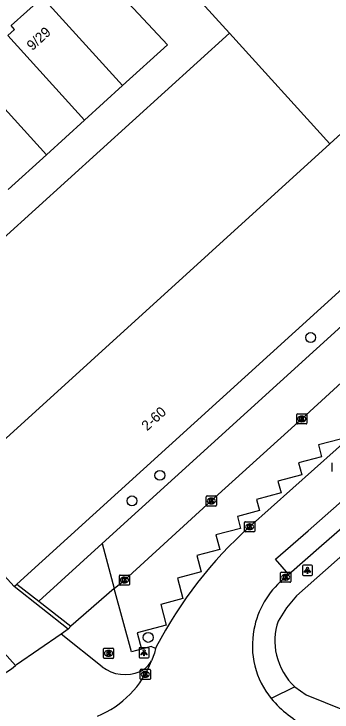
# Model space of a CAD drawing. Extents: x 161354 to 161876, y 382161 to 382804.
# Drawn here: x 161643.4 to 161674.9, y 382511.3 to 382580.4 of the extents above; entities that cross this region are included whole.
import ezdxf

# ---------------------------------------------------------------- set-up
doc = ezdxf.new("R2010")
doc.units = 0
for name, color, linetype in [('IMGEO_Boom', 7, 'Continuous'), ('IMGEO_Kolk', 7, 'Continuous'), ('IMGEO_Lichtpunt', 7, 'Continuous'), ('IMGEO_Muur', 7, 'Continuous'), ('IMGEO_Pand', 7, 'Continuous'), ('IMGEO_Pand_nummerreeks', 7, 'Continuous'), ('IMGEO_Parkeervlak_gesloten', 7, 'Continuous'), ('IMGEO_Parkeervlak_open', 7, 'Continuous'), ('IMGEO_Rijbaan_lokaal_gesloten', 7, 'Continuous'), ('IMGEO_Rijbaan_lokaal_open', 7, 'Continuous'), ('IMGEO_Rioolput', 7, 'Continuous'), ('IMGEO_Voetpad_open', 7, 'Continuous')]:
    doc.layers.add(name, color=color, linetype=linetype)

msp = doc.modelspace()

# ---------------------------------------------------------------- linework, layer by layer
at = {"layer": 'IMGEO_Boom'}
for centre in [(161672.751, 382548.367), (161657.819, 382534.735), (161655.061, 382532.208), (161656.668, 382518.703)]:
    msp.add_circle(centre, 0.489, dxfattribs=at)
at = {"layer": 'IMGEO_Kolk'}
for p, q in [((161671.374, 382539.891), (161671.374, 382540.743)), ((161671.449, 382540.817), (161672.301, 382540.817)), ((161671.862, 382540.597), (161671.887, 382540.597)), ((161672.375, 382540.743), (161672.375, 382539.891)), ((161672.301, 382539.817), (161671.449, 382539.817)), ((161671.885, 382540.037), (161671.86, 382540.037)), ((161662.415, 382531.773), (161662.415, 382532.625)), ((161662.49, 382532.699), (161663.342, 382532.699)), ((161662.903, 382532.479), (161662.928, 382532.479)), ((161663.416, 382532.625), (161663.416, 382531.773)), ((161663.342, 382531.699), (161662.49, 382531.699)), ((161662.926, 382531.919), (161662.901, 382531.919)), ((161666.211, 382529.218), (161666.211, 382530.07)), ((161666.286, 382530.144), (161667.138, 382530.144)), ((161667.212, 382530.07), (161667.212, 382529.218)), ((161666.722, 382529.364), (161666.697, 382529.364)), ((161666.699, 382529.924), (161666.724, 382529.924)), ((161667.138, 382529.144), (161666.286, 382529.144)), ((161653.814, 382523.95), (161653.814, 382524.802)), ((161653.889, 382524.876), (161654.741, 382524.876)), ((161654.302, 382524.656), (161654.327, 382524.656)), ((161654.815, 382524.802), (161654.815, 382523.95)), ((161669.778, 382524.229), (161669.778, 382525.081)), ((161669.853, 382525.155), (161670.705, 382525.155)), ((161670.266, 382524.935), (161670.291, 382524.935)), ((161670.779, 382525.081), (161670.779, 382524.229)), ((161654.741, 382523.876), (161653.889, 382523.876)), ((161654.325, 382524.096), (161654.3, 382524.096)), ((161670.705, 382524.155), (161669.853, 382524.155)), ((161670.289, 382524.375), (161670.264, 382524.375)), ((161655.96, 382515.548), (161656.812, 382515.548)), ((161655.885, 382514.622), (161655.885, 382515.474)), ((161656.373, 382515.328), (161656.398, 382515.328)), ((161656.886, 382515.474), (161656.886, 382514.622)), ((161656.812, 382514.548), (161655.96, 382514.548)), ((161656.396, 382514.768), (161656.371, 382514.768))]:
    msp.add_line(p, q, dxfattribs=at)
for points in [[(161671.374, 382539.891), (161671.374, 382540.743)], [(161671.449, 382540.817), (161672.301, 382540.817)], [(161671.695, 382540.517), (161671.818, 382540.517), (161671.818, 382540.366), (161671.948, 382540.517), (161672.112, 382540.517), (161671.966, 382540.366), (161672.119, 382540.117), (161671.967, 382540.117), (161671.882, 382540.281), (161671.818, 382540.214), (161671.818, 382540.117), (161671.695, 382540.117), (161671.695, 382540.517)], [(161672.375, 382540.743), (161672.375, 382539.891)], [(161672.301, 382539.817), (161671.449, 382539.817)], [(161662.415, 382531.773), (161662.415, 382532.625)], [(161662.49, 382532.699), (161663.342, 382532.699)], [(161662.736, 382532.399), (161662.859, 382532.399), (161662.859, 382532.248), (161662.989, 382532.399), (161663.153, 382532.399), (161663.007, 382532.248), (161663.16, 382531.999), (161663.008, 382531.999), (161662.923, 382532.163), (161662.859, 382532.096), (161662.859, 382531.999), (161662.736, 382531.999), (161662.736, 382532.399)], [(161663.416, 382532.625), (161663.416, 382531.773)], [(161663.342, 382531.699), (161662.49, 382531.699)], [(161666.211, 382529.218), (161666.211, 382530.07)], [(161666.286, 382530.144), (161667.138, 382530.144)], [(161667.212, 382530.07), (161667.212, 382529.218)], [(161666.532, 382529.844), (161666.655, 382529.844), (161666.655, 382529.693), (161666.785, 382529.844), (161666.949, 382529.844), (161666.803, 382529.693), (161666.956, 382529.444), (161666.804, 382529.444), (161666.719, 382529.608), (161666.655, 382529.541), (161666.655, 382529.444), (161666.532, 382529.444), (161666.532, 382529.844)], [(161667.138, 382529.144), (161666.286, 382529.144)], [(161653.814, 382523.95), (161653.814, 382524.802)], [(161653.889, 382524.876), (161654.741, 382524.876)], [(161654.135, 382524.576), (161654.258, 382524.576), (161654.258, 382524.425), (161654.388, 382524.576), (161654.552, 382524.576), (161654.406, 382524.425), (161654.559, 382524.176), (161654.407, 382524.176), (161654.322, 382524.34), (161654.258, 382524.273), (161654.258, 382524.176), (161654.135, 382524.176), (161654.135, 382524.576)], [(161654.815, 382524.802), (161654.815, 382523.95)], [(161669.778, 382524.229), (161669.778, 382525.081)], [(161669.853, 382525.155), (161670.705, 382525.155)], [(161670.099, 382524.855), (161670.222, 382524.855), (161670.222, 382524.704), (161670.352, 382524.855), (161670.516, 382524.855), (161670.37, 382524.704), (161670.523, 382524.455), (161670.371, 382524.455), (161670.286, 382524.619), (161670.222, 382524.552), (161670.222, 382524.455), (161670.099, 382524.455), (161670.099, 382524.855)], [(161670.779, 382525.081), (161670.779, 382524.229)], [(161654.741, 382523.876), (161653.889, 382523.876)], [(161670.705, 382524.155), (161669.853, 382524.155)], [(161655.96, 382515.548), (161656.812, 382515.548)], [(161655.885, 382514.622), (161655.885, 382515.474)], [(161656.206, 382515.248), (161656.329, 382515.248), (161656.329, 382515.097), (161656.459, 382515.248), (161656.623, 382515.248), (161656.477, 382515.097), (161656.63, 382514.848), (161656.478, 382514.848), (161656.393, 382515.012), (161656.329, 382514.945), (161656.329, 382514.848), (161656.206, 382514.848), (161656.206, 382515.248)], [(161656.886, 382515.474), (161656.886, 382514.622)], [(161656.812, 382514.548), (161655.96, 382514.548)]]:
    msp.add_lwpolyline(points, dxfattribs=at)
for centre, start, end in [((161671.451, 382540.741), 91.55205, 178.44795), ((161671.451, 382540.741), 91.55205, 178.44795), ((161672.299, 382540.741), 1.55205, 88.44795), ((161672.299, 382540.741), 1.55205, 88.44795), ((161671.451, 382539.893), 181.55205, 268.44795), ((161671.451, 382539.893), 181.55205, 268.44795), ((161672.299, 382539.893), 271.55205, 358.44795), ((161672.299, 382539.893), 271.55205, 358.44795), ((161662.492, 382532.623), 91.55205, 178.44795), ((161662.492, 382532.623), 91.55205, 178.44795), ((161663.34, 382532.623), 1.55205, 88.44795), ((161663.34, 382532.623), 1.55205, 88.44795), ((161662.492, 382531.775), 181.55205, 268.44795), ((161662.492, 382531.775), 181.55205, 268.44795), ((161663.34, 382531.775), 271.55205, 358.44795), ((161663.34, 382531.775), 271.55205, 358.44795), ((161666.288, 382530.068), 91.55205, 178.44795), ((161666.288, 382530.068), 91.55205, 178.44795), ((161667.136, 382530.068), 1.55205, 88.44795), ((161667.136, 382530.068), 1.55205, 88.44795), ((161666.288, 382529.22), 181.55205, 268.44795), ((161666.288, 382529.22), 181.55205, 268.44795), ((161667.136, 382529.22), 271.55205, 358.44795), ((161667.136, 382529.22), 271.55205, 358.44795), ((161653.891, 382524.8), 91.55205, 178.44795), ((161653.891, 382524.8), 91.55205, 178.44795), ((161654.739, 382524.8), 1.55205, 88.44795), ((161654.739, 382524.8), 1.55205, 88.44795), ((161669.855, 382525.079), 91.55205, 178.44795), ((161669.855, 382525.079), 91.55205, 178.44795), ((161670.703, 382525.079), 1.55205, 88.44795), ((161670.703, 382525.079), 1.55205, 88.44795), ((161653.891, 382523.952), 181.55205, 268.44795), ((161653.891, 382523.952), 181.55205, 268.44795), ((161654.739, 382523.952), 271.55205, 358.44795), ((161654.739, 382523.952), 271.55205, 358.44795), ((161669.855, 382524.231), 181.55205, 268.44795), ((161669.855, 382524.231), 181.55205, 268.44795), ((161670.703, 382524.231), 271.55205, 358.44795), ((161670.703, 382524.231), 271.55205, 358.44795), ((161655.962, 382515.472), 91.55205, 178.44795), ((161655.962, 382515.472), 91.55205, 178.44795), ((161656.81, 382515.472), 1.55205, 88.44795), ((161656.81, 382515.472), 1.55205, 88.44795), ((161655.962, 382514.624), 181.55205, 268.44795), ((161655.962, 382514.624), 181.55205, 268.44795), ((161656.81, 382514.624), 271.55205, 358.44795), ((161656.81, 382514.624), 271.55205, 358.44795)]:
    msp.add_arc(centre, 0.0765, start, end, dxfattribs=at)
for centre, major_axis, ratio, start_param, end_param in [((161671.861, 382540.317), (-0.387, 0.002), 0.722429, 4.712389, 7.853982), ((161671.886, 382540.317), (-0.39, 0.002), 0.717154, 1.570796, 4.712389), ((161662.902, 382532.199), (-0.387, 0.002), 0.722429, 4.712389, 7.853982), ((161662.927, 382532.199), (-0.39, 0.002), 0.717154, 1.570796, 4.712389), ((161666.698, 382529.644), (-0.387, 0.002), 0.722429, 4.712389, 7.853982), ((161666.723, 382529.644), (-0.39, 0.002), 0.717154, 1.570796, 4.712389), ((161654.301, 382524.376), (-0.387, 0.002), 0.722429, 4.712389, 7.853982), ((161654.326, 382524.376), (-0.39, 0.002), 0.717154, 1.570796, 4.712389), ((161670.265, 382524.655), (-0.387, 0.002), 0.722429, 4.712389, 7.853982), ((161670.29, 382524.655), (-0.39, 0.002), 0.717154, 1.570796, 4.712389), ((161656.372, 382515.048), (-0.387, 0.002), 0.722429, 4.712389, 7.853982), ((161656.397, 382515.048), (-0.39, 0.002), 0.717154, 1.570796, 4.712389)]:
    msp.add_ellipse(centre, major_axis=major_axis, ratio=ratio, start_param=start_param, end_param=end_param, dxfattribs=at)
at = {"layer": 'IMGEO_Lichtpunt'}
for p, q in [((161671.937, 382525.741), (161671.937, 382524.934)), ((161671.937, 382525.741), (161671.937, 382524.934)), ((161672.839, 382525.836), (161672.031, 382525.836)), ((161672.839, 382525.836), (161672.031, 382525.836)), ((161672.933, 382524.934), (161672.933, 382525.741)), ((161672.933, 382524.934), (161672.933, 382525.741)), ((161672.031, 382524.84), (161672.839, 382524.84)), ((161672.031, 382524.84), (161672.839, 382524.84)), ((161655.757, 382517.591), (161655.757, 382516.784)), ((161655.757, 382517.591), (161655.757, 382516.784)), ((161656.659, 382517.686), (161655.851, 382517.686)), ((161656.659, 382517.686), (161655.851, 382517.686)), ((161656.753, 382516.784), (161656.753, 382517.591)), ((161656.753, 382516.784), (161656.753, 382517.591)), ((161655.851, 382516.69), (161656.659, 382516.69)), ((161655.851, 382516.69), (161656.659, 382516.69))]:
    msp.add_line(p, q, dxfattribs=at)
for points in [[(161672.311, 382525.405), (161672.35, 382525.377), (161672.162, 382525.115), (161672.124, 382525.142), (161672.311, 382525.405)], [(161672.413, 382525.357), (161672.46, 382525.357), (161672.46, 382525.035), (161672.413, 382525.035), (161672.413, 382525.357)], [(161672.523, 382525.377), (161672.561, 382525.404), (161672.748, 382525.142), (161672.709, 382525.114), (161672.523, 382525.377)], [(161656.131, 382517.255), (161656.17, 382517.227), (161655.982, 382516.965), (161655.944, 382516.992), (161656.131, 382517.255)], [(161656.233, 382517.207), (161656.28, 382517.207), (161656.28, 382516.885), (161656.233, 382516.885), (161656.233, 382517.207)], [(161656.343, 382517.227), (161656.381, 382517.254), (161656.568, 382516.992), (161656.529, 382516.964), (161656.343, 382517.227)]]:
    msp.add_lwpolyline(points, dxfattribs=at)
for centre in [(161672.436, 382525.539), (161656.256, 382517.389)]:
    msp.add_circle(centre, 0.0994, dxfattribs=at)
for centre, start, end in [((161672.031, 382525.741), 90, 180), ((161672.031, 382525.741), 90, 180), ((161672.839, 382525.741), 0, 90), ((161672.839, 382525.741), 0, 90), ((161672.031, 382524.934), 180, 270), ((161672.031, 382524.934), 180, 270), ((161672.839, 382524.934), 270, 0), ((161672.839, 382524.934), 270, 360), ((161655.851, 382517.591), 90, 180), ((161655.851, 382517.591), 90, 180), ((161656.659, 382517.591), 0, 90), ((161656.659, 382517.591), 0, 90), ((161655.851, 382516.784), 180, 270), ((161655.851, 382516.784), 180, 270), ((161656.659, 382516.784), 270, 0), ((161656.659, 382516.784), 270, 360)]:
    msp.add_arc(centre, 0.0946, start, end, dxfattribs=at)
at = {"layer": 'IMGEO_Muur'}
for points in [[(161643.672, 382523.978), (161645.836, 382522.287)], [(161648.744, 382519.518), (161643.393, 382523.725)], [(161645.836, 382522.287), (161649.018, 382519.8)], [(161649.018, 382519.8), (161648.744, 382519.518)]]:
    msp.add_lwpolyline(points, dxfattribs=at)
at = {"layer": 'IMGEO_Pand'}
for points in [[(161664.71, 382578.468), (161661.6, 382581.894), (161665.593, 382585.519), (161669.295, 382588.879), (161675.871, 382594.848)], [(161646.188, 382582.043), (161649.968, 382585.484), (161650.322, 382585.095), (161650.859, 382585.596), (161658.581, 382577.332), (161654.132, 382573.291)], [(161642.757, 382578.236), (161643.428, 382578.834), (161643.099, 382579.23), (161646.188, 382582.043)], [(161646.188, 382582.043), (161654.132, 382573.291)], [(161664.71, 382578.468), (161674.636, 382567.532)], [(161650.358, 382569.861), (161642.757, 382578.236)], [(161638.636, 382575.188), (161646.582, 382566.431)], [(161654.132, 382573.291), (161650.358, 382569.861)], [(161684.928, 382563.407), (161678.388, 382570.921), (161674.636, 382567.532)], [(161650.358, 382569.861), (161646.582, 382566.431)], [(161674.636, 382567.532), (161638.938, 382535.131), (161638.008, 382536.155), (161634.759, 382533.207), (161640.057, 382527.369), (161643.393, 382523.725)], [(161646.582, 382566.431), (161642.81, 382563.004)], [(161643.672, 382523.978), (161676.253, 382553.55), (161682.265, 382559.016)], [(161643.393, 382523.725), (161643.672, 382523.978)]]:
    msp.add_lwpolyline(points, dxfattribs=at)
at = {"layer": 'IMGEO_Parkeervlak_gesloten'}
msp.add_lwpolyline([(161643.533, 382515.936), (161628.206, 382532.98), (161623.055, 382540.753), (161664.71, 382578.468)], dxfattribs=at)
at = {"layer": 'IMGEO_Parkeervlak_open'}
msp.add_lwpolyline([(161675.696, 382538.314), (161673.531, 382537.738), (161673.839, 382536.58), (161671.551, 382535.971), (161671.864, 382534.794), (161669.509, 382534.167), (161669.818, 382533.006), (161667.397, 382532.361), (161667.694, 382531.243), (161665.493, 382530.658), (161665.805, 382529.486), (161663.371, 382528.839), (161663.753, 382527.403), (161661.475, 382526.796), (161661.907, 382525.174), (161659.573, 382524.553), (161660.108, 382522.54), (161657.902, 382521.952), (161658.443, 382519.918), (161655.565, 382519.153), (161655.991, 382517.551)], dxfattribs=at)
at = {"layer": 'IMGEO_Rijbaan_lokaal_gesloten'}
for points in [[(161694.524, 382554.274), (161691.651, 382551.884), (161690.206, 382550.598), (161681.712, 382543.025), (161666.712, 382529.643)], [(161670.597, 382524.931), (161669.286, 382526.443), (161672.516, 382529.253), (161677.271, 382533.418), (161681.896, 382537.521), (161686.794, 382541.797), (161691.965, 382546.197), (161696.498, 382550.18), (161697.808, 382548.669)], [(161670.026, 382524.435), (161670.597, 382524.931)], [(161657.401, 382517.61), (161657.294, 382517.138), (161656.991, 382516.392)], [(161657.469, 382517.761), (161657.401, 382517.61)]]:
    msp.add_lwpolyline(points, dxfattribs=at)
for centre, radius, start, end in [((161694.552, 382498.45), 41.81, 131.7494, 152.49196), ((161675.414, 382517.973), 8.414, 129.81838, 169.60969), ((161675.236, 382517.879), 8.256, 168.74647, 219.29448), ((161647.988, 382519.82), 9.633, 292.25063, 339.15488), ((161678.097, 382520.597), 12.195, 220.66495, 242.42362)]:
    msp.add_arc(centre, radius, start, end, dxfattribs=at)
at = {"layer": 'IMGEO_Rijbaan_lokaal_open'}
for points in [[(161682.265, 382559.016), (161684.128, 382557.046), (161652.099, 382527.995)], [(161653.308, 382523.528), (161654.315, 382524.377), (161662.915, 382532.2), (161671.874, 382540.317), (161680.506, 382548.198), (161692.48, 382559.009)], [(161652.099, 382527.995), (161645.836, 382522.287)], [(161652.099, 382527.995), (161653.308, 382523.528)], [(161653.308, 382523.528), (161649.018, 382519.8)]]:
    msp.add_lwpolyline(points, dxfattribs=at)
at = {"layer": 'IMGEO_Rioolput'}
for p, q in [((161674.869, 382535.131), (161674.869, 382535.983)), ((161652.313, 382517.633), (161653.165, 382517.633)), ((161652.238, 382516.707), (161652.238, 382517.559)), ((161652.726, 382517.413), (161652.751, 382517.413)), ((161653.239, 382517.559), (161653.239, 382516.707)), ((161653.165, 382516.633), (161652.313, 382516.633)), ((161652.749, 382516.853), (161652.724, 382516.853))]:
    msp.add_line(p, q, dxfattribs=at)
for points in [[(161674.869, 382535.131), (161674.869, 382535.983)], [(161652.313, 382517.633), (161653.165, 382517.633)], [(161652.238, 382516.707), (161652.238, 382517.559)], [(161652.827, 382517.331), (161652.575, 382517.333), (161652.575, 382516.933)], [(161652.575, 382516.933), (161652.699, 382516.933), (161652.699, 382517.095), (161652.71, 382517.095)], [(161652.753, 382517.252), (161652.699, 382517.252), (161652.699, 382517.171)], [(161652.699, 382517.171), (161652.751, 382517.171)], [(161652.757, 382517.066), (161652.828, 382516.933), (161652.968, 382516.933), (161652.903, 382517.059)], [(161653.239, 382517.559), (161653.239, 382516.707)], [(161653.165, 382516.633), (161652.313, 382516.633)]]:
    msp.add_lwpolyline(points, dxfattribs=at)
for centre, radius, start, end in [((161652.315, 382517.557), 0.0765, 91.55205, 178.44795), ((161652.315, 382517.557), 0.0765, 91.55205, 178.44795), ((161653.163, 382517.557), 0.0765, 1.55205, 88.44795), ((161653.163, 382517.557), 0.0765, 1.55205, 88.44795), ((161652.709, 382517.042), 0.0533, 26.02933, 88.69889), ((161652.735, 382517.36), 0.19, 274.7715, 282.96867), ((161652.759, 382517.156), 0.0964, 77.00612, 93.18647), ((161652.773, 382517.213), 0.0378, 276.66336, 79.67722), ((161652.826, 382517.221), 0.109, 350.36119, 89.41601), ((161652.824, 382517.221), 0.112, 277.58423, 350.98172), ((161652.808, 382517.006), 0.108, 29.51342, 73.79051), ((161652.315, 382516.709), 0.0765, 181.55205, 268.44795), ((161652.315, 382516.709), 0.0765, 181.55205, 268.44795), ((161653.163, 382516.709), 0.0765, 271.55205, 358.44795), ((161653.163, 382516.709), 0.0765, 271.55205, 358.44795)]:
    msp.add_arc(centre, radius, start, end, dxfattribs=at)
for centre, major_axis, ratio, start_param, end_param in [((161652.725, 382517.133), (-0.387, 0.002), 0.722429, 4.712389, 7.853982), ((161652.75, 382517.133), (-0.39, 0.002), 0.717154, 1.570796, 4.712389)]:
    msp.add_ellipse(centre, major_axis=major_axis, ratio=ratio, start_param=start_param, end_param=end_param, dxfattribs=at)
at = {"layer": 'IMGEO_Voetpad_open'}
for points in [[(161702.444, 382550.002), (161681.121, 382531.471), (161671.366, 382522.817), (161670.351, 382521.638), (161669.529, 382520.317)], [(161684.328, 382536.99), (161683.217, 382536.02), (161678.594, 382531.918), (161673.831, 382527.746), (161670.597, 382524.931)], [(161655.991, 382517.551), (161655.007, 382517.289), (161653.308, 382523.528)], [(161648.064, 382519.038), (161643.62, 382516.005), (161643.533, 382515.936)], [(161648.744, 382519.518), (161648.064, 382519.038)], [(161652.1, 382515.786), (161648.064, 382519.038)], [(161657.401, 382517.61), (161656.976, 382517.813), (161655.991, 382517.551)], [(161639.588, 382513.357), (161643.126, 382515.61), (161643.533, 382515.936)], [(161671.192, 382513.811), (161668.846, 382512.65)], [(161671.192, 382513.811), (161672.294, 382513.039), (161676.079, 382511.506), (161686.582, 382508.346), (161693.296, 382505.713), (161699.526, 382502.596), (161701.857, 382501.312), (161704.194, 382500.041), (161707.056, 382498.523), (161714.17, 382494.92), (161716.027, 382493.968), (161718.402, 382492.765), (161721.484, 382491.299)]]:
    msp.add_lwpolyline(points, dxfattribs=at)
for centre, radius, start, end in [((161674.782, 382518.398), 5.592, 159.93584, 195.0334), ((161675.503, 382518.391), 6.29, 193.26441, 226.73155), ((161654.698, 382517.675), 2.628, 296.44804, 330.78307), ((161654.391, 382518.861), 3.834, 233.30633, 292.6533)]:
    msp.add_arc(centre, radius, start, end, dxfattribs=at)

# ---------------------------------------------------------------- texts
at = {"layer": 'IMGEO_Pand_nummerreeks'}
for s, rotation, p in [('9/29', 42.21781, (161645.19, 382576.694)), ('2-60', 42.22809, (161656.558, 382539.078))]:
    msp.add_text(s, height=1, rotation=rotation, dxfattribs=at).set_placement(p)

doc.saveas('drawing.dxf')
